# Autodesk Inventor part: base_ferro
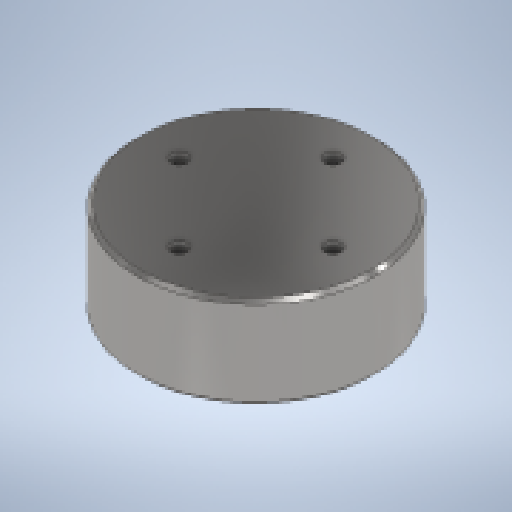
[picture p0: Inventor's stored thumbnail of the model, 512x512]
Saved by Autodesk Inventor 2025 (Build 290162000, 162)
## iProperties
Created: 2026-01
Part Number: base_ferro
Material: Acciaio
Document SubType Name: Modeling
Designer: Ryzen5700u
Density: 7.85 g/cm^3
Appearance: Acciaio - Lucido
Mass: 7039.17 g
Surface Area: 726.938 cm^2
Volume: 896.709 cm^3
Author: Ryzen5700u
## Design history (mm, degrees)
sketch "Schizzo1"
  geometry: C1 r 50 at (0, 0); 1 further point
  constraints: 1 centre point, 1 coincident
  dimensions: "d0" = 100 diameter of C1
extrude "Estrusione1" new body sketch "Schizzo1" distance "d1" = 50; taper "d2" = 0 deg
sketch "Schizzo3"
  geometry: L1 (0, 0)-(42, 0)
  constraints: 2 end point, 1 horizontal
  dimensions: "d14" = 42 distance of L1.start L1.end
hole "Foro2" sketch "Schizzo3" at (42, 0) diameter "d15" = 5.3; stored, may be unused: countersink angle "d19" = 90 deg, drill point angle "d21" = 118 deg; dims "d16" = 6, "d17" = 9, "d18" = 15, "d20" = 8
pattern_circular "Serie circolare2" dims angle "d23" = 360 deg
sketch "Schizzo4"
  geometry: C1 r 65 at (0, 0); C2 r 50 at (0, 0) reference; 1 further point
  constraints: 1 centre point, 1 coincident
  dimensions: "d25" = 130 diameter of C1
extrude "Estrusione2" join sketch "Schizzo4" stored distance "d26" = 10; taper "d27" = 0 deg
chamfer "Smusso1" distance "d28" = 2; stored, may be unused: second distance "d29" = 2, angle "d30" = 45 deg
node "Solido1"
